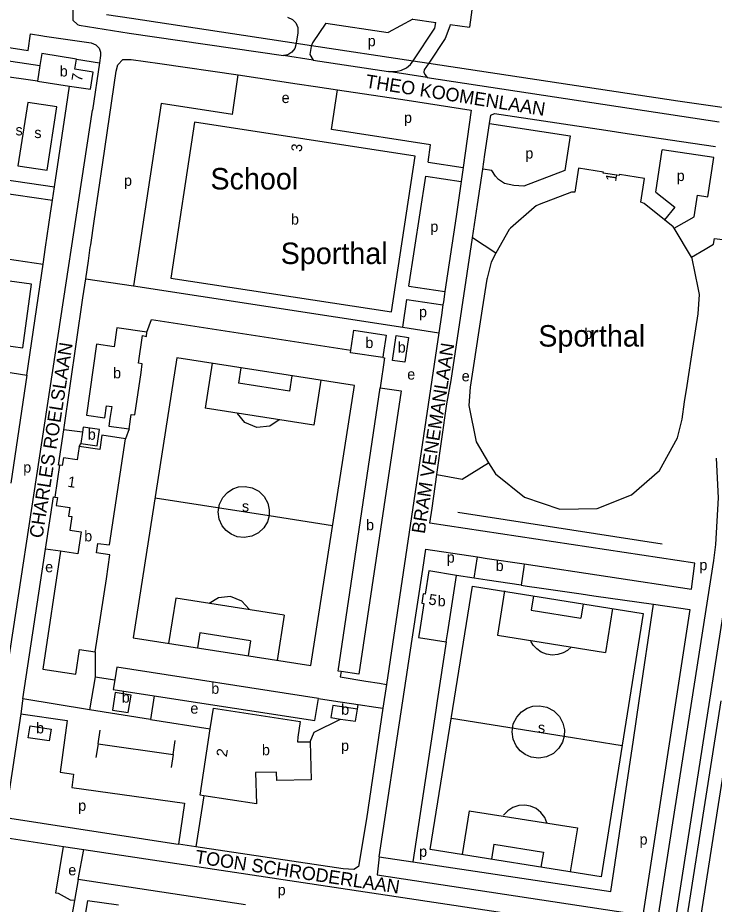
# Model space of a CAD drawing. Extents: x 161093 to 163177, y 379000 to 380904.
# Drawn here: x 161325.1 to 161584.6, y 380148.5 to 380478.7 of the extents above; entities that cross this region are included whole.
import ezdxf

# ---------------------------------------------------------------- set-up
doc = ezdxf.new("R2010")
doc.units = 0
for name, color, linetype in [('BLT_Basislijn', 7, 'Continuous'), ('BLT_Bebouwing', 7, 'Continuous'), ('BLT_Bebouwing_beschrifting', 7, 'Continuous'), ('BLT_Centroide', 7, 'Continuous'), ('BLT_Huisnummer', 7, 'Continuous'), ('BLT_Straatnaam', 7, 'Continuous')]:
    doc.layers.add(name, color=color, linetype=linetype)

msp = doc.modelspace()

# ---------------------------------------------------------------- linework, layer by layer
at = {"layer": 'BLT_Basislijn'}
for p, q in [((161495.47, 380490.36), (161493.39, 380475.21)), ((161358.16, 380479.89), (161367.5, 380478.53)), ((161367.5, 380478.53), (161428.85, 380469.26)), ((161472.31, 380478.1), (161463.17, 380473.19)), ((161472.31, 380478.1), (161480.89, 380476.92)), ((161439.9, 380476.69), (161463.17, 380473.19)), ((161486.2, 380476.19), (161493.39, 380475.21)), ((161366.62, 380472.88), (161424.13, 380464.58)), ((161428.85, 380469.26), (161434.6, 380468.39)), ((161434.6, 380468.39), (161472.44, 380462.67)), ((161299.8, 380466.04), (161333.35, 380460.86)), ((161435.16, 380462.92), (161424.13, 380464.58)), ((161347.03, 380463.28), (161355.58, 380461.89)), ((161355.58, 380461.89), (161352.93, 380444.22)), ((161435.16, 380462.92), (161463.2, 380458.64)), ((161472.44, 380462.67), (161478.25, 380461.79)), ((161332.45, 380455.09), (161310.37, 380458.16)), ((161405.16, 380442.65), (161407.19, 380457.36)), ((161407.19, 380457.36), (161429.24, 380454.09)), ((161477.62, 380456.45), (161463.2, 380458.64)), ((161429.24, 380454.09), (161436.09, 380453.08)), ((161477.62, 380456.45), (161586.43, 380439.89)), ((161343.28, 380445.66), (161344.4, 380453.23)), ((161442.03, 380437), (161444.23, 380451.87)), ((161319.48, 380224.32), (161352.93, 380444.22)), ((161338.82, 380415.69), (161343.28, 380445.66)), ((161499.19, 380427.71), (161500.93, 380439.34)), ((161544.22, 380436.81), (161552.19, 380435.62)), ((161552.19, 380435.62), (161585.13, 380430.69)), ((161498.38, 380422.35), (161499.19, 380427.71)), ((161477.97, 380424.94), (161491.05, 380422.92)), ((161491.05, 380422.92), (161490.31, 380417.69)), ((161496.41, 380409.18), (161498.38, 380422.35)), ((161477.16, 380419.68), (161490.31, 380417.69)), ((161300.65, 380416.24), (161338.09, 380410.75)), ((161338.09, 380410.75), (161338.82, 380415.69)), ((161337.37, 380405.92), (161338.09, 380410.75)), ((161335.49, 380393.22), (161337.37, 380405.92)), ((161488.45, 380404.72), (161484.28, 380376.7)), ((161503.3, 380390.95), (161494.53, 380396.69)), ((161334.56, 380386.89), (161335.49, 380393.22)), ((161351.44, 380388.21), (161352.16, 380393.16)), ((161350.46, 380381.5), (161351.44, 380388.21)), ((161328.55, 380345.63), (161334.56, 380386.89)), ((161349.42, 380374.36), (161350.46, 380381.5)), ((161368.21, 380378.79), (161468.55, 380363.43)), ((161470.89, 380378.71), (161484.28, 380376.7)), ((161484.28, 380376.7), (161483.71, 380372.91)), ((161342.25, 380325.25), (161349.42, 380374.36)), ((161470.13, 380373.76), (161483.54, 380371.75)), ((161483.54, 380371.75), (161482.97, 380367.96)), ((161483.71, 380372.91), (161483.54, 380371.75)), ((161482.97, 380367.96), (161481.99, 380361.37)), ((161373.21, 380361.61), (161375.02, 380366.35)), ((161375.02, 380366.35), (161449.19, 380354.92)), ((161468.55, 380363.43), (161481.99, 380361.37)), ((161481.99, 380361.37), (161480.26, 380349.72)), ((161289.31, 380351.48), (161328.55, 380345.63)), ((161461.73, 380352.04), (161460.16, 380340.9)), ((161461.13, 380352.13), (161461.73, 380352.04)), ((161397.59, 380349.99), (161394.99, 380333.28)), ((161408.29, 380348.32), (161407.4, 380342.6)), ((161480.26, 380349.72), (161462.48, 380230.43)), ((161328.55, 380345.63), (161322.52, 380305.29)), ((161427.24, 380345.37), (161426.35, 380339.65)), ((161426.35, 380339.65), (161407.4, 380342.6)), ((161438.06, 380343.69), (161435.46, 380326.97)), ((161435.46, 380326.97), (161394.99, 380333.28)), ((161349.25, 380324.29), (161342.25, 380325.25)), ((161366.61, 380325.62), (161365.33, 380321.9)), ((161479.48, 380296.03), (161481.27, 380308.58)), ((161418.75, 380293.18), (161376.27, 380299.79)), ((161442.39, 380289.5), (161418.79, 380293.17)), ((161489.04, 380294.55), (161565.21, 380282.76)), ((161327, 380224.98), (161335.49, 380280.77)), ((161341.07, 380280.01), (161335.49, 380280.77)), ((161495.18, 380269.99), (161488.62, 380270.98)), ((161512.62, 380267.36), (161514.92, 380267.03)), ((161514.92, 380267.03), (161519.33, 380266.39)), ((161519.33, 380266.39), (161535.09, 380264.12)), ((161383.97, 380262.51), (161381.34, 380245.65)), ((161424.44, 380256.21), (161383.97, 380262.51)), ((161506.46, 380265.26), (161503.81, 380248.72)), ((161517.28, 380263.34), (161516.43, 380258)), ((161535.09, 380264.12), (161539.71, 380263.45)), ((161539.71, 380263.45), (161561.93, 380260.24)), ((161535.75, 380260.39), (161534.89, 380255.04)), ((161556.7, 380224.32), (161561.93, 380260.24)), ((161424.44, 380256.21), (161421.82, 380239.34)), ((161516.43, 380258), (161534.89, 380255.04)), ((161546.69, 380258.64), (161544.07, 380242.28)), ((161392.93, 380249.64), (161392.05, 380243.98)), ((161411.87, 380246.69), (161392.93, 380249.64)), ((161411.87, 380246.69), (161410.99, 380241.03)), ((161484.77, 380246.31), (161481.44, 380224.32)), ((161503.81, 380248.72), (161544.07, 380242.28)), ((161354.01, 380242.52), (161353.96, 380233.27)), ((161353.96, 380233.27), (161351.89, 380220.92)), ((161353.96, 380233.27), (161361.26, 380232.15)), ((161454.77, 380231.67), (161459.88, 380230.85)), ((161459.88, 380230.85), (161462.48, 380230.43)), ((161462.48, 380230.43), (161461.16, 380221.56)), ((161375.92, 380226.15), (161374.57, 380217.37)), ((161326.91, 380224.32), (161326.24, 380219.49)), ((161327, 380224.98), (161326.91, 380224.32)), ((161437.12, 380225.18), (161442.82, 380224.32)), ((161442.82, 380224.32), (161451.93, 380222.95)), ((161451.67, 380221.22), (161451.93, 380222.95)), ((161451.93, 380222.95), (161458.53, 380221.96)), ((161459.76, 380166.2), (161468.62, 380224.32)), ((161481.44, 380224.32), (161480.9, 380220.77)), ((161554.59, 380209.82), (161556.7, 380224.32)), ((161587.04, 380224.32), (161579.39, 380175.41)), ((161592.12, 380224.32), (161584.33, 380174.64)), ((161458.53, 380221.96), (161461.16, 380221.56)), ((161480.9, 380220.77), (161472.35, 380164.32)), ((161486.67, 380217.86), (161528.69, 380211.14)), ((161355.04, 380208.29), (161355.78, 380213.33)), ((161382.99, 380204.35), (161383.81, 380209.51)), ((161528.74, 380211.13), (161550.28, 380207.68)), ((161546.06, 380153.27), (161554.59, 380209.82)), ((161355.04, 380208.29), (161354.28, 380203.23)), ((161355.04, 380208.29), (161382.99, 380204.35)), ((161382.99, 380204.35), (161382.27, 380199.43)), ((161493.36, 380183.38), (161490.74, 380167.01)), ((161493.36, 380183.38), (161533.61, 380176.94)), ((161533.61, 380176.94), (161530.99, 380160.57)), ((161579.39, 380175.41), (161574.2, 380142.05)), ((161584.33, 380174.64), (161579.15, 380141.3)), ((161342.15, 380170.09), (161349.77, 380168.95)), ((161502.49, 380170.92), (161501.59, 380165.27)), ((161502.49, 380170.92), (161520.96, 380167.96)), ((161347.62, 380157.69), (161349.77, 380168.95)), ((161349.77, 380168.95), (161557.02, 380137.81)), ((161520.96, 380167.96), (161520.06, 380162.32)), ((161459.76, 380166.2), (161472.35, 380164.32)), ((161472.35, 380164.32), (161546.06, 380153.27)), ((161347.62, 380157.69), (161346.22, 380149.9)), ((161410.03, 380148.29), (161347.62, 380157.69)), ((161346.22, 380149.9), (161341.26, 380122.41))]:
    msp.add_line(p, q, dxfattribs=at)
for points in [[(161213.84, 380483.12), (161215.09, 380483.55), (161218.52, 380483.64), (161295.56, 380471.7), (161296.49, 380477.82), (161301.35, 380477.09), (161300.47, 380470.93), (161328.98, 380466.5), (161329.9, 380472.69), (161334.48, 380471.98), (161335.13, 380471.86), (161352.54, 380469.32), (161354.21, 380468.64), (161355.48, 380467.36), (161355.94, 380465.82), (161356, 380464.58), (161355.58, 380461.89)], [(161345.65, 380481.46), (161345.62, 380477.82), (161347.33, 380476.11), (161348.07, 380475.86), (161366.62, 380472.88)], [(161425.62, 380478.84), (161427.47, 380478.02), (161428.69, 380476.79), (161429.42, 380474.99), (161429.5, 380473.03), (161428.85, 380469.26)], [(161472.44, 380462.67), (161480.47, 380474.83), (161480.89, 380476.92)], [(161439.9, 380476.69), (161434.96, 380469.28), (161434.6, 380468.39)], [(161486.2, 380476.19), (161486.09, 380475.55), (161484.33, 380470.96), (161478.25, 380461.79)], [(161428.85, 380469.26), (161428.82, 380469.09), (161428.31, 380467.22), (161427.26, 380465.83), (161425.81, 380464.91), (161424.13, 380464.58)], [(161434.6, 380468.39), (161434.44, 380467.98), (161433.97, 380464.95), (161435.16, 380462.92)], [(161356.85, 380424.71), (161361.84, 380458.74), (161362.44, 380461.16), (161364.26, 380463.17), (161367.44, 380463.07), (161378.07, 380461.68), (161407.19, 380457.36)], [(161463.2, 380458.64), (161465.97, 380458.68), (161468.05, 380459.13), (161469.93, 380459.98), (161471.51, 380461.26), (161472.44, 380462.67)], [(161478.25, 380461.79), (161476.59, 380459.28), (161476.45, 380458.45), (161476.73, 380457.54), (161477.62, 380456.45)], [(161478.25, 380461.79), (161571.03, 380447.77), (161600.55, 380443.47)], [(161310.37, 380458.16), (161304.76, 380420.69), (161338.82, 380415.69)], [(161436.09, 380453.08), (161444.23, 380451.87)], [(161444.23, 380451.87), (161470.27, 380448.01), (161494.11, 380444.26), (161491.05, 380422.92)], [(161328.86, 380447.16), (161325.21, 380423.58), (161336.05, 380421.9), (161339.7, 380445.48), (161328.86, 380447.16)], [(161405.16, 380442.65), (161378.61, 380446.71), (161368.21, 380378.79)], [(161500.93, 380439.34), (161501.4, 380442.46), (161502.74, 380443.02), (161544.22, 380436.81)], [(161500.93, 380439.34), (161530.9, 380434.75)], [(161477.97, 380424.94), (161478.95, 380431.35), (161442.03, 380437)], [(161530.9, 380434.75), (161528.89, 380421.85)], [(161562.85, 380413.74), (161565.24, 380429.51)], [(161569.64, 380400.29), (161577.09, 380404.53), (161578.38, 380412.58), (161582.18, 380412.03), (161584.42, 380426.6), (161565.24, 380429.51)], [(161584.36, 380394.3), (161584.67, 380396.47), (161590.84, 380395.68), (161595.18, 380429.19)], [(161352.16, 380393.16), (161352.31, 380394.17), (161353.61, 380402.92), (161356.85, 380424.71)], [(161528.89, 380421.85), (161513.72, 380415.97), (161509.99, 380416.22), (161506.51, 380416.99), (161504.22, 380418.41), (161503.13, 380419.68), (161501.71, 380421.79), (161498.38, 380422.35)], [(161470.89, 380378.71), (161477.16, 380419.68)], [(161490.31, 380417.69), (161488.45, 380404.72)], [(161562.85, 380413.74), (161569.89, 380408.09), (161566.1, 380403.39)], [(161494.53, 380396.69), (161496.41, 380409.18)], [(161481.27, 380308.58), (161485.03, 380334.9), (161486.56, 380343.56), (161494.53, 380396.69)], [(161297.61, 380392.33), (161334.56, 380386.89)], [(161576.09, 380389.57), (161581.19, 380392.48), (161584.36, 380394.3)], [(161350.46, 380381.5), (161368.21, 380378.79)], [(161319.38, 380380.94), (161316.14, 380357.3), (161327, 380355.81), (161330.24, 380379.45), (161319.38, 380380.94)], [(161468.55, 380363.43), (161470.13, 380373.76)], [(161570.23, 380142.65), (161590.32, 380271.48), (161592.03, 380282.42), (161592.92, 380291.45), (161593.03, 380310.33), (161592.17, 380323.23), (161591.97, 380337.06), (161592.71, 380349.18), (161594.53, 380361.65), (161595.36, 380361.52)], [(161422.56, 380328.98), (161419, 380326.55), (161414.15, 380326.02), (161409.67, 380327.96), (161406.99, 380331.34)], [(161340.74, 380312.02), (161340.25, 380312.09), (161342.25, 380325.25)], [(161348, 380319.01), (161348.61, 380320.14), (161348.61, 380320.14)], [(161481.27, 380308.58), (161490.76, 380306.89), (161500.57, 380312.98)], [(161563.68, 380143.64), (161569.99, 380184.41), (161584.44, 380276.56), (161585.22, 380282.45), (161586.24, 380299.89), (161585.47, 380314.7)], [(161418.76, 380293.13), (161418.13, 380290.93), (161416.85, 380288.74), (161414.86, 380286.84), (161412.32, 380285.56), (161409.53, 380285.09), (161406.87, 380285.41), (161404.59, 380286.35), (161402.81, 380287.68), (161401.29, 380289.51), (161400.21, 380291.9), (161399.81, 380294.66), (161400.26, 380297.48), (161401.48, 380299.99), (161403.24, 380301.93), (161405.24, 380303.21), (161407.34, 380303.93), (161409.8, 380304.13), (161412.44, 380303.63), (161414.94, 380302.32), (161416.97, 380300.33), (161418.28, 380297.91), (161418.84, 380295.43), (161418.76, 380293.15)], [(161335.49, 380280.77), (161338.45, 380300.25), (161338.89, 380300.18)], [(161577.43, 380275.54), (161478.69, 380290.5), (161479.48, 380296.03)], [(161468.62, 380224.32), (161472.12, 380247.27), (161476.08, 380273.23), (161477.19, 380280.79), (161496.39, 380277.87)], [(161513.84, 380275.25), (161576.13, 380265.91), (161577.43, 380275.54)], [(161411.32, 380258.39), (161408.6, 380261.4), (161404.42, 380263.09), (161399.94, 380262.67), (161396.47, 380260.57)], [(161561.93, 380260.24), (161575.46, 380258.29), (161558.05, 380144.49)], [(161531.28, 380244.23), (161529.95, 380243.06), (161528.28, 380242.11), (161526.34, 380241.5), (161524.22, 380241.33), (161522.1, 380241.66), (161520.13, 380242.44), (161518.46, 380243.6), (161517.15, 380245), (161516.22, 380246.51)], [(161445.63, 380235.15), (161445.22, 380233.21), (161454.77, 380231.67)], [(161351.89, 380220.92), (161327, 380224.98)], [(161326.24, 380219.49), (161320.93, 380184.07), (161320.96, 380181.79), (161322.14, 380180.53), (161384, 380171.06), (161385.05, 380170.9)], [(161326.24, 380219.49), (161343.49, 380216.92), (161340.92, 380197.67), (161345.89, 380196.96), (161345.25, 380192.02), (161387.24, 380186.22)], [(161374.57, 380217.37), (161351.89, 380220.92)], [(161461.16, 380221.56), (161455.02, 380180.31), (161452.09, 380162.6), (161450.34, 380161.48), (161446.39, 380161.72), (161391.48, 380169.89)], [(161528.7, 380211.11), (161528.05, 380208.86), (161526.72, 380206.62), (161524.67, 380204.69), (161522.06, 380203.38), (161519.2, 380202.91), (161516.46, 380203.26), (161514.14, 380204.24), (161512.31, 380205.61), (161510.77, 380207.49), (161509.67, 380209.95), (161509.28, 380212.78), (161509.74, 380215.67), (161511.01, 380218.24), (161512.82, 380220.22), (161514.88, 380221.53), (161517.04, 380222.25), (161519.56, 380222.45), (161522.27, 380221.92), (161524.83, 380220.57), (161526.9, 380218.51), (161528.24, 380216.03), (161528.8, 380213.48), (161528.71, 380211.14)], [(161374.57, 380217.37), (161396.87, 380213.88)], [(161434.11, 380209.07), (161435.61, 380212.68), (161445.33, 380217.52)], [(161394.48, 380188.94), (161391.48, 380169.89)], [(161387.24, 380186.22), (161385.05, 380170.9)], [(161522.3, 380178.87), (161521.44, 380180.9), (161520.05, 380182.74), (161518.24, 380184.17), (161516.17, 380185.09), (161514.02, 380185.46), (161511.76, 380185.3), (161509.57, 380184.56), (161507.65, 380183.3), (161506.15, 380181.67)], [(161315.69, 380164.58), (161317.84, 380173.75), (161342.15, 380170.09)], [(161346.22, 380149.9), (161344.83, 380150.11), (161340.29, 380152.57), (161339.38, 380152.7), (161342.15, 380170.09)], [(161391.48, 380169.89), (161385.05, 380170.9)], [(161459.76, 380166.2), (161459.05, 380159.46), (161558.05, 380144.49)], [(161362.67, 380148.13), (161351.1, 380149.85), (161343.38, 380104.69)]]:
    msp.add_lwpolyline(points, dxfattribs=at)
for points in [[(161384.4, 380352.06), (161368.15, 380247.69), (161434.28, 380237.39), (161450.53, 380341.76)], [(161494.52, 380266.99), (161558.15, 380256.82), (161542.45, 380158.72), (161478.83, 380168.9)]]:
    msp.add_lwpolyline(points, close=True, dxfattribs=at)
at = {"layer": 'BLT_Bebouwing'}
for p, q in [((161347.03, 380463.28), (161334.05, 380465.35)), ((161332.45, 380455.09), (161344.4, 380453.23)), ((161344.4, 380453.23), (161352.22, 380452.03)), ((161517.56, 380408.03), (161508.72, 380400.29)), ((161576.09, 380389.57), (161569.64, 380400.29)), ((161574.54, 380341.77), (161576.68, 380355.61)), ((161461.3, 380353.21), (161461.13, 380352.13)), ((161460.16, 380340.9), (161468.03, 380339.71)), ((161349.25, 380324.29), (161348.61, 380320.14)), ((161365.33, 380321.9), (161356.51, 380323.21)), ((161348.61, 380320.14), (161354.69, 380319.23)), ((161495.18, 380269.99), (161496.39, 380277.87)), ((161513.67, 380274.11), (161512.62, 380267.36)), ((161513.84, 380275.25), (161513.67, 380274.11)), ((161485.37, 380250), (161488.62, 380270.98)), ((161484.77, 380246.31), (161485.37, 380250)), ((161362.04, 380236.83), (161361.26, 380232.15)), ((161437.12, 380225.18), (161362.04, 380236.83)), ((161361.26, 380232.15), (161360.64, 380228.48)), ((161360.64, 380228.48), (161375.92, 380226.15))]:
    msp.add_line(p, q, dxfattribs=at)
for points in [[(161334.05, 380465.35), (161333.35, 380460.86)], [(161333.35, 380460.86), (161332.45, 380455.09)], [(161353.21, 380458.44), (161346.45, 380459.48), (161347.03, 380463.28)], [(161352.22, 380452.03), (161353.21, 380458.44)], [(161566.1, 380403.39), (161558.52, 380409.49), (161557.23, 380409.98), (161558.57, 380418.84), (161549.28, 380420.29), (161549.22, 380419.88), (161543.29, 380420.77), (161543.35, 380421.18), (161534.08, 380422.65), (161532.7, 380413.75), (161531.43, 380413.72), (161519.37, 380409.08)], [(161519.37, 380409.08), (161518.3, 380408.67), (161517.56, 380408.03)], [(161569.64, 380400.29), (161569.36, 380400.77), (161566.1, 380403.39)], [(161508.72, 380400.29), (161508.23, 380399.86), (161503.3, 380390.95)], [(161503.3, 380390.95), (161501.47, 380387.64), (161500, 380381.64), (161499.92, 380381.33), (161498.17, 380370.28), (161496.69, 380360.65), (161495.12, 380350.75), (161493.69, 380341.14), (161493.24, 380334.25), (161495.91, 380320.69), (161500.57, 380312.98)], [(161578.61, 380378.14), (161576.44, 380388.98), (161576.09, 380389.57)], [(161576.68, 380355.61), (161578.65, 380368.42), (161579.12, 380375.57), (161578.61, 380378.14)], [(161373.21, 380361.61), (161362.07, 380363.23), (161361.05, 380356.13), (161354.51, 380357.06), (161350.76, 380330.73), (161357.6, 380329.74), (161358.24, 380334.16), (161360.15, 380333.89), (161359.48, 380329.47)], [(161366.61, 380325.62), (161367.4, 380330.98), (161368.81, 380330.79), (161371.07, 380346.52), (161371.54, 380349.76), (161370.13, 380350), (161371.61, 380360.3), (161373.15, 380359.93), (161373.21, 380361.61)], [(161449.19, 380354.92), (161450.32, 380362.31), (161462.41, 380360.52), (161461.3, 380353.21)], [(161461.13, 380352.13), (161449.04, 380353.92), (161449.19, 380354.92)], [(161500.57, 380312.98), (161503.1, 380308.8), (161513.91, 380300.14), (161527.03, 380295.67), (161540.97, 380295.96), (161553.84, 380300.96), (161564.24, 380310.09), (161570.94, 380322.28), (161572.6, 380329.15), (161573.59, 380335.65), (161574.54, 380341.77)], [(161445.63, 380235.15), (161444.44, 380235.36), (161460.16, 380340.9)], [(161468.03, 380339.71), (161452.19, 380234.17), (161445.63, 380235.15)], [(161359.48, 380329.47), (161359.06, 380326.56), (161366.61, 380325.62)], [(161354.69, 380319.23), (161355.63, 380325.32), (161355.63, 380325.32), (161349.55, 380326.24), (161349.25, 380324.29)], [(161354.01, 380242.52), (161358.22, 380269.74), (161359.45, 380278.62), (161354.46, 380279.37), (161354.98, 380282.94), (161359.34, 380282.33), (161365.33, 380321.9)], [(161356.51, 380323.21), (161355.68, 380317.86)], [(161348, 380319.01), (161347.25, 380314.06), (161342.15, 380314.84), (161341.7, 380311.87), (161340.74, 380312.02)], [(161355.68, 380317.86), (161348, 380319.01)], [(161340.74, 380312.02), (161338.89, 380300.18)], [(161338.89, 380300.18), (161339.88, 380300.03), (161339.42, 380297.01), (161344.53, 380296.24), (161344.06, 380293.1), (161345.3, 380292.92)], [(161345.3, 380292.92), (161344.53, 380287.82), (161348.74, 380287.19), (161347.51, 380279.05), (161341.07, 380280.01)], [(161341.07, 380280.01), (161334.47, 380236.03), (161346.8, 380234.18)], [(161496.39, 380277.87), (161500, 380277.33), (161513.84, 380275.25)], [(161488.62, 380270.98), (161478.26, 380272.69), (161476.94, 380264.03), (161476.2, 380264.14), (161475.65, 380260.61), (161476.43, 380260.5), (161474.83, 380250)], [(161512.62, 380267.36), (161500, 380269.27), (161495.18, 380269.99)], [(161474.83, 380250), (161474.47, 380247.89), (161484.77, 380246.31)], [(161346.8, 380234.18), (161348.18, 380243.41), (161354.01, 380242.52)], [(161375.92, 380226.15), (161435.8, 380216.96), (161437.12, 380225.18)], [(161396.87, 380213.88), (161398.07, 380221.61), (161430.36, 380216.65)], [(161451.67, 380221.22), (161442.48, 380222.6), (161441.8, 380218.05), (161445.33, 380217.52)], [(161445.33, 380217.52), (161451, 380216.68), (161451.67, 380221.22)], [(161430.36, 380216.65), (161429.44, 380210.72), (161429.37, 380209.01), (161434.11, 380209.07)], [(161329.03, 380210.53), (161329.7, 380214.95), (161337.56, 380213.77), (161336.89, 380209.34), (161329.03, 380210.53)], [(161394.48, 380188.94), (161393.06, 380189.16), (161396.87, 380213.88)], [(161434.11, 380209.07), (161434.4, 380194.9), (161421.66, 380194.63), (161421.59, 380197.69), (161413.71, 380197.56), (161414.09, 380185.9), (161394.48, 380188.94)]]:
    msp.add_lwpolyline(points, dxfattribs=at)
for points in [[(161391.02, 380439.75), (161382.13, 380381.67), (161464.36, 380369.12), (161473.23, 380427.17)], [(161466.15, 380360.3), (161470.71, 380359.63), (161469.33, 380350.43), (161464.8, 380351.09)], [(161361.42, 380227.33), (161360.41, 380220.83), (161366.32, 380219.93), (161367.34, 380226.42)]]:
    msp.add_lwpolyline(points, close=True, dxfattribs=at)

# ---------------------------------------------------------------- texts
at = {"layer": 'BLT_Bebouwing_beschrifting'}
for s, p in [('School', (161396.91, 380414.72)), ('Sporthal', (161423.09, 380386.95)), ('Sporthal', (161519.06, 380356.21))]:
    msp.add_text(s, height=8, dxfattribs=at).set_placement(p)
at = {"layer": 'BLT_Centroide'}
for s, p in [('p', (161455.51, 380468.06)), ('b', (161340.79, 380456.8)), ('e', (161423.44, 380446.91)), ('p', (161469.03, 380439.51)), ('s', (161324.3, 380434.86)), ('s', (161331.31, 380433.87)), ('p', (161514.23, 380426.22)), ('p', (161570.63, 380417.87)), ('p', (161364.72, 380416.09)), ('b', (161426.91, 380401.65)), ('p', (161478.83, 380398.94)), ('p', (161474.61, 380367.17)), ('b', (161536.19, 380359.08)), ('b', (161454.63, 380355.67)), ('b', (161466.7, 380353.99)), ('b', (161360.65, 380344.41)), ('e', (161470.23, 380343.94)), ('e', (161490.53, 380343.26)), ('b', (161351.23, 380321.52)), ('p', (161327.17, 380309.29)), ('s', (161408.64, 380294.78)), ('b', (161454.9, 380287.83)), ('b', (161349.89, 380283.67)), ('p', (161484.96, 380275.73)), ('b', (161503.17, 380272.62)), ('p', (161579.08, 380272.93)), ('e', (161335.35, 380272.17)), ('b', (161481.55, 380259.48)), ('b', (161397.21, 380226.91)), ('b', (161363.88, 380223.63)), ('b', (161445.63, 380219.1)), ('e', (161389.44, 380219.51)), ('b', (161331.96, 380212.16)), ('s', (161518.93, 380212.32)), ('b', (161416.1, 380204.03)), ('p', (161445.58, 380205.64)), ('p', (161347.65, 380183.33)), ('p', (161556.78, 380170.72)), ('p', (161474.67, 380166.21)), ('e', (161343.96, 380159.29)), ('p', (161421.97, 380151.89))]:
    msp.add_text(s, height=4, dxfattribs=at).set_placement(p)
at = {"layer": 'BLT_Huisnummer'}
for s, rotation, p in [('7', 81.2785, (161349.05, 380454.75)), ('3', 83.5743, (161430.9, 380428.59)), ('1', 81.3947, (161548.04, 380417.49)), ('1', 351.5796, (161343.51, 380304.02)), ('5', 351.2869, (161477.98, 380260.2)), ('2', 81.2745, (161403, 380203.24))]:
    msp.add_text(s, height=4, rotation=rotation, dxfattribs=at).set_placement(p)
at = {"layer": 'BLT_Straatnaam'}
for s, height, rotation, p in [('THEO KOOMENLAAN', 4.9999, 350.9764, (161454.44, 380452.71)), ('CHARLES ROELSLAAN', 5, 81.1659, (161334.34, 380284.65)), ('BRAM VENEMANLAAN', 5, 81.1117, (161476.74, 380286.3)), ('TOON SCHRODERLAAN', 4.9999, 351.4692, (161390.97, 380163.89))]:
    msp.add_text(s, height=height, rotation=rotation, dxfattribs=at).set_placement(p)

doc.saveas('drawing.dxf')
